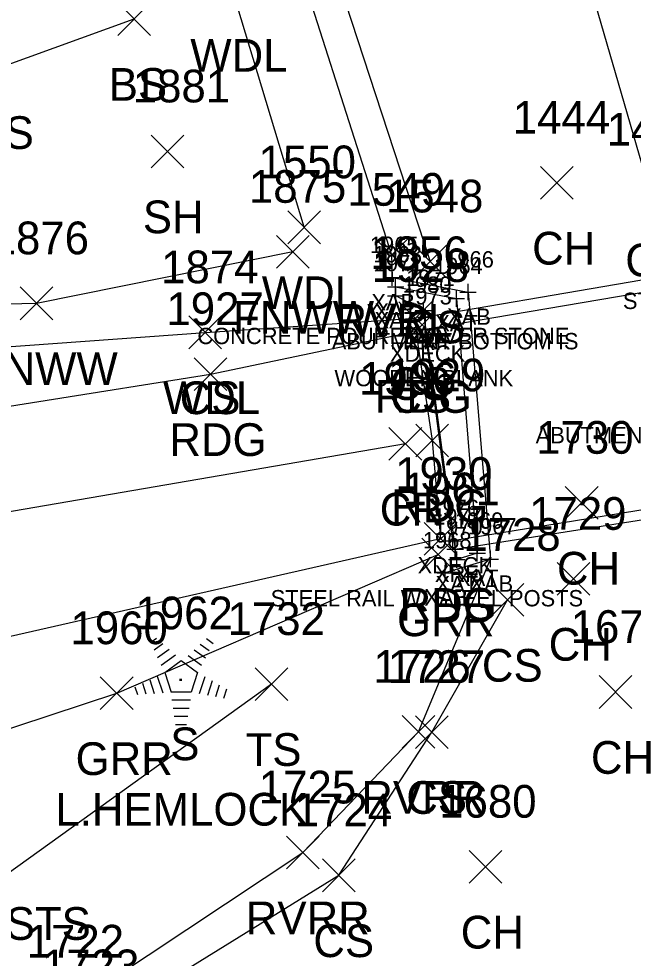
# Model space of a CAD drawing. Extents: x 1621633 to 1624015, y 417863 to 420979.
# Drawn here: x 1621947.4 to 1621985, y 418067.9 to 418125.3 of the extents above; entities that cross this region are included whole.
import ezdxf

# ---------------------------------------------------------------- set-up
doc = ezdxf.new("R2010")
doc.units = 0
for name, color, linetype in [('B_A', 7, 'Continuous'), ('B_C', 7, 'Continuous'), ('B_I', 7, 'Continuous'), ('B_TIC', 7, 'Continuous'), ('BELB', 7, 'Continuous'), ('BR', 7, 'Continuous'), ('BSUBM', 7, 'Continuous'), ('L_A', 7, 'Continuous'), ('L_C', 7, 'Continuous'), ('L_I', 7, 'Continuous'), ('L_TIC', 7, 'Continuous'), ('LAWA', 7, 'Continuous'), ('LAWE', 7, 'Continuous'), ('LELB', 7, 'Continuous'), ('LFNC', 7, 'Continuous'), ('LTC', 7, 'Continuous'), ('P_A', 7, 'Continuous'), ('P_I', 7, 'Continuous'), ('P_TIC', 7, 'Continuous'), ('PEU', 7, 'Continuous'), ('PRC', 7, 'Continuous'), ('R_A', 7, 'Continuous'), ('R_C', 7, 'Continuous'), ('R_I', 7, 'Continuous'), ('R_TIC', 7, 'Continuous'), ('RGR', 7, 'Continuous')]:
    doc.layers.add(name, color=color, linetype=linetype)

msp = doc.modelspace()

# ---------------------------------------------------------------- linework, layer by layer
at = {"layer": 'B_TIC'}
for p, q in [((1621970.273, 418109.501), (1621970.349, 418109.501)), ((1621970.477, 418108.931), (1621970.553, 418108.931)), ((1621974.904, 418108.613), (1621974.98, 418108.613)), ((1621970.487, 418108.387), (1621970.563, 418108.387)), ((1621974.195, 418108.215), (1621974.27, 418108.215)), ((1621972.178, 418107.487), (1621972.254, 418107.487)), ((1621972.304, 418107.07), (1621972.38, 418107.07)), ((1621972.283, 418106.356), (1621972.358, 418106.356)), ((1621973.978, 418093.412), (1621974.053, 418093.412)), ((1621974.116, 418092.897), (1621974.192, 418092.897)), ((1621975.464, 418092.646), (1621975.539, 418092.646)), ((1621974.209, 418092.261), (1621974.284, 418092.261)), ((1621976.265, 418092.293), (1621976.341, 418092.293)), ((1621973.512, 418091.444), (1621973.587, 418091.444))]:
    msp.add_line(p, q, dxfattribs=at)
for points in [[(1621970.27, 418109.001), (1621970.27, 418110.001)], [(1621969.77, 418109.501), (1621970.77, 418109.501)], [(1621970.474, 418108.431), (1621970.474, 418109.431)], [(1621974.901, 418108.113), (1621974.901, 418109.113)], [(1621969.974, 418108.931), (1621970.974, 418108.931)], [(1621970.484, 418107.887), (1621970.484, 418108.887)], [(1621974.191, 418107.715), (1621974.191, 418108.715)], [(1621974.401, 418108.613), (1621975.401, 418108.613)], [(1621969.984, 418108.387), (1621970.984, 418108.387)], [(1621972.175, 418106.987), (1621972.175, 418107.987)], [(1621973.691, 418108.215), (1621974.691, 418108.215)], [(1621971.675, 418107.487), (1621972.675, 418107.487)], [(1621972.301, 418106.57), (1621972.301, 418107.57)], [(1621971.801, 418107.07), (1621972.801, 418107.07)], [(1621972.279, 418105.856), (1621972.279, 418106.856)], [(1621971.779, 418106.356), (1621972.779, 418106.356)], [(1621973.974, 418092.912), (1621973.974, 418093.912)], [(1621973.474, 418093.412), (1621974.474, 418093.412)], [(1621973.613, 418092.897), (1621974.613, 418092.897)], [(1621974.113, 418092.397), (1621974.113, 418093.397)], [(1621975.461, 418092.146), (1621975.461, 418093.146)], [(1621974.205, 418091.761), (1621974.205, 418092.761)], [(1621974.961, 418092.646), (1621975.961, 418092.646)], [(1621976.262, 418091.793), (1621976.262, 418092.793)], [(1621973.508, 418090.944), (1621973.508, 418091.944)], [(1621973.705, 418092.261), (1621974.705, 418092.261)], [(1621975.762, 418092.293), (1621976.762, 418092.293)], [(1621973.008, 418091.444), (1621974.008, 418091.444)]]:
    msp.add_lwpolyline(points, dxfattribs=at)
at = {"layer": 'BELB'}
for points in [[(1621972.279, 418106.356), (1621995.663, 418110.32), (1621997.337, 418097.222), (1621973.974, 418093.412)], [(1621973.974, 418093.412), (1621972.279, 418106.356)]]:
    msp.add_lwpolyline(points, dxfattribs=at)
at = {"layer": 'BR'}
for points in [[(1621995.641, 418111.077), (1621972.301, 418107.07)], [(1621974.113, 418092.897), (1621997.518, 418096.593)]]:
    msp.add_lwpolyline(points, dxfattribs=at)
at = {"layer": 'BSUBM'}
for points in [[(1621970.27, 418109.501), (1621974.901, 418108.613), (1621976.262, 418092.293), (1621973.508, 418091.444)], [(1621970.474, 418108.931), (1621974.191, 418108.215), (1621975.461, 418092.646), (1621974.205, 418092.261), (1621972.175, 418107.487), (1621970.484, 418108.387)]]:
    msp.add_lwpolyline(points, dxfattribs=at)
at = {"layer": 'L_TIC'}
for points in [[(1621953.501, 418124.31), (1621955.501, 418126.31)], [(1621955.501, 418124.31), (1621953.501, 418126.31)], [(1621955.534, 418116.211), (1621957.534, 418118.211)], [(1621957.534, 418116.211), (1621955.534, 418118.211)], [(1621979.328, 418114.296), (1621981.328, 418116.296)], [(1621981.328, 418114.296), (1621979.328, 418116.296)], [(1621963.876, 418111.573), (1621965.876, 418113.573)], [(1621965.876, 418111.573), (1621963.876, 418113.573)], [(1621963.197, 418110.074), (1621965.197, 418112.074)], [(1621965.197, 418110.074), (1621963.197, 418112.074)], [(1621969.23, 418109.893), (1621971.23, 418111.893)], [(1621971.23, 418109.893), (1621969.23, 418111.893)], [(1621971.578, 418109.484), (1621973.578, 418111.484)], [(1621973.578, 418109.484), (1621971.578, 418111.484)], [(1621947.53, 418106.925), (1621949.53, 418108.925)], [(1621949.53, 418106.925), (1621947.53, 418108.925)], [(1621970.677, 418106.015), (1621972.677, 418108.015)], [(1621972.677, 418106.015), (1621970.677, 418108.015)], [(1621957.835, 418105.152), (1621959.835, 418107.152)], [(1621959.835, 418105.152), (1621957.835, 418107.152)], [(1621957.835, 418105.152), (1621959.835, 418107.152)], [(1621959.835, 418105.152), (1621957.835, 418107.152)], [(1621970.708, 418105.231), (1621972.708, 418107.231)], [(1621972.708, 418105.231), (1621970.708, 418107.231)], [(1621980.843, 418094.729), (1621982.843, 418096.729)], [(1621982.843, 418094.729), (1621980.843, 418096.729)], [(1621980.338, 418090.078), (1621982.338, 418092.078)], [(1621982.338, 418090.078), (1621980.338, 418092.078)], [(1621976.304, 418088.793), (1621978.304, 418090.793)], [(1621978.304, 418088.793), (1621976.304, 418090.793)], [(1621961.893, 418083.645), (1621963.893, 418085.645)], [(1621963.893, 418083.645), (1621961.893, 418085.645)], [(1621982.92, 418083.162), (1621984.92, 418085.162)], [(1621984.92, 418083.162), (1621982.92, 418085.162)], [(1621970.864, 418080.724), (1621972.864, 418082.724)], [(1621972.864, 418080.724), (1621970.864, 418082.724)], [(1621971.682, 418080.713), (1621973.682, 418082.713)], [(1621973.682, 418080.713), (1621971.682, 418082.713)], [(1621963.804, 418073.349), (1621965.804, 418075.349)], [(1621965.804, 418073.349), (1621963.804, 418075.349)], [(1621966.003, 418071.955), (1621968.003, 418073.955)], [(1621968.003, 418071.955), (1621966.003, 418073.955)], [(1621974.963, 418072.479), (1621976.963, 418074.479)], [(1621976.963, 418072.479), (1621974.963, 418074.479)]]:
    msp.add_lwpolyline(points, dxfattribs=at)
at = {"layer": 'LAWA'}
for points in [[(1621956.585, 418284.614), (1621944.789, 418263.744), (1621937.989, 418240.815), (1621923.643, 418212.076), (1621903.114, 418191.442), (1621882.695, 418166.672), (1621873.439, 418154.294), (1621850.988, 418135.574), (1621826.172, 418116.057), (1621804.716, 418096.141), (1621776.821, 418074.388), (1621781.781, 418070.723), (1621808.711, 418078.699), (1621829.621, 418083.556), (1621862.329, 418091.327), (1621892.285, 418098.274), (1621914.935, 418102.809), (1621920.305, 418103.098), (1621927.789, 418103.902), (1621958.835, 418106.152)], [(1621964.876, 418112.573), (1621960.506, 418127.086), (1621958.473, 418132.299), (1621952.202, 418163.991), (1621942.417, 418191.539), (1621933.842, 418203.578)]]:
    msp.add_lwpolyline(points, dxfattribs=at)
at = {"layer": 'LAWE'}
for points in [[(1622333.173, 418232.978), (1622304.922, 418224.429), (1622278.58, 418222.596), (1622250.586, 418234.065), (1622231.085, 418250.898), (1622207.089, 418257.628), (1622185.142, 418265.615), (1622157.854, 418271.291), (1622128.424, 418279.107), (1622109.176, 418281.03), (1622103.422, 418276.532), (1622081.068, 418269.588), (1622054.892, 418266.851), (1622024.679, 418262.775), (1621999.348, 418261.337), (1621980.097, 418259.353), (1621959.539, 418247.527), (1621949.109, 418230.907), (1621945.674, 418206.622), (1621950.844, 418182.298), (1621958.694, 418157.035), (1621962.917, 418133.775), (1621970.23, 418110.893)], [(1621970.23, 418110.893), (1621970.27, 418109.501)], [(1621971.864, 418081.724), (1621976.262, 418092.293)], [(1621682.822, 417967.998), (1621698.064, 417979.126), (1621716.448, 417990.621), (1621740.687, 418004.296), (1621760.276, 418012.676), (1621779.786, 418018.1), (1621807.782, 418023.044), (1621832.841, 418028.899), (1621852.452, 418034.783), (1621876.37, 418040.125), (1621904.646, 418043.594), (1621931.259, 418052.925), (1621950.617, 418064.927), (1621964.804, 418074.349), (1621971.864, 418081.724)]]:
    msp.add_lwpolyline(points, dxfattribs=at)
at = {"layer": 'LELB'}
for points in [[(1621986.067, 418114.571), (1621980.007, 418135.511), (1621971.795, 418158.969), (1621964.778, 418178.351), (1621962.014, 418198.432), (1621960.296, 418210.777), (1621971.297, 418225.2), (1621983.839, 418236.143), (1622007.179, 418245.448), (1622025.653, 418246.508), (1622054.037, 418255.072), (1622065.318, 418256.151)], [(1621951.89, 418230.385), (1621950.814, 418206.602), (1621953.261, 418182.888), (1621961.465, 418157.615), (1621964.444, 418135.417), (1621972.578, 418110.484)], [(1621925.719, 418114.299), (1621946.353, 418122.363), (1621954.501, 418125.31)], [(1621958.835, 418106.152), (1621971.677, 418107.015), (1621971.708, 418106.231)], [(1621714.218, 417979.319), (1621742.211, 418002.577), (1621762.579, 418009.214), (1621780.28, 418013.608), (1621808.258, 418019.376), (1621833.473, 418026.83), (1621853.516, 418030.646), (1621878.098, 418035.973), (1621904.446, 418042.094), (1621933.372, 418049.997), (1621951.553, 418063.416), (1621967.003, 418072.955), (1621972.682, 418081.713), (1621977.304, 418089.793)], [(1621962.893, 418084.645), (1621941.499, 418069.284), (1621934.526, 418059.292), (1621911.153, 418049.766), (1621884.836, 418045.66), (1621868.891, 418041.418), (1621850.259, 418038.198), (1621830.712, 418031.899), (1621803.346, 418026.98), (1621784.312, 418024.309)]]:
    msp.add_lwpolyline(points, dxfattribs=at)
at = {"layer": 'LFNC'}
msp.add_lwpolyline([(1621964.197, 418111.074), (1621948.53, 418107.925), (1621925.05, 418107.389), (1621910.629, 418106.254), (1621880.442, 418100.757), (1621858.02, 418096.026), (1621836.432, 418089.427), (1621812.807, 418084.09), (1621788.073, 418077.584)], dxfattribs=at)
at = {"layer": 'LTC'}
for p, q in [((1621955.509, 418087.202), (1621955.864, 418087.46)), ((1621958.907, 418087.442), (1621959.326, 418087.138)), ((1621955.719, 418086.737), (1621956.248, 418087.121)), ((1621955.928, 418086.271), (1621956.632, 418086.782)), ((1621958.165, 418086.746), (1621958.844, 418086.252)), ((1621958.536, 418087.094), (1621959.086, 418086.695)), ((1621956.138, 418085.805), (1621957.016, 418086.443)), ((1621956.362, 418085.35), (1621957.374, 418086.085)), ((1621957.374, 418086.085), (1621958.371, 418085.36)), ((1621957.794, 418086.397), (1621958.604, 418085.809)), ((1621955.452, 418084.915), (1621955.724, 418084.079)), ((1621955.908, 418085.131), (1621956.239, 418084.112)), ((1621956.362, 418085.35), (1621956.749, 418084.157)), ((1621958.371, 418085.36), (1621957.98, 418084.157)), ((1621958.809, 418085.089), (1621958.471, 418084.049)), ((1621954.541, 418084.481), (1621954.694, 418084.013)), ((1621954.997, 418084.698), (1621955.209, 418084.046)), ((1621959.253, 418084.838), (1621958.966, 418083.954)), ((1621959.698, 418084.588), (1621959.461, 418083.859)), ((1621960.142, 418084.338), (1621959.955, 418083.764)), ((1621957.98, 418084.157), (1621956.749, 418084.157)), ((1621957.941, 418083.657), (1621956.797, 418083.657)), ((1621957.858, 418083.157), (1621956.869, 418083.157)), ((1621957.774, 418082.657), (1621956.942, 418082.657)), ((1621957.69, 418082.157), (1621957.015, 418082.157))]:
    msp.add_line(p, q, dxfattribs=at)
at = {"layer": 'P_TIC'}
for points in [[(1621970.708, 418105.231), (1621972.708, 418107.231)], [(1621972.708, 418105.231), (1621970.708, 418107.231)], [(1621958.157, 418102.592), (1621960.157, 418104.592)], [(1621960.157, 418102.592), (1621958.157, 418104.592)], [(1621971.706, 418098.544), (1621973.706, 418100.544)], [(1621973.706, 418098.544), (1621971.706, 418100.544)], [(1621970.067, 418098.341), (1621972.067, 418100.341)], [(1621972.067, 418098.341), (1621970.067, 418100.341)], [(1621972.225, 418092.52), (1621974.225, 418094.52)], [(1621974.225, 418092.52), (1621972.225, 418094.52)]]:
    msp.add_lwpolyline(points, dxfattribs=at)
at = {"layer": 'PEU'}
msp.add_lwpolyline([(1621862.236, 418084.699), (1621894.034, 418092.423), (1621927.67, 418098.576), (1621959.157, 418103.592), (1621971.708, 418106.231), (1621972.706, 418099.544), (1621973.225, 418093.52), (1621943.584, 418086.799), (1621912.204, 418078.592), (1621880.997, 418070.288)], dxfattribs=at)
at = {"layer": 'PRC'}
msp.add_lwpolyline([(1621971.067, 418099.341), (1621938.438, 418093.726), (1621906.629, 418086.952), (1621874.869, 418079.941), (1621842.519, 418071.194), (1621811.531, 418061.42), (1621780.514, 418050.109), (1621750.947, 418035.3), (1621723.041, 418018.53), (1621696.18, 418000.53), (1621670.933, 417981.571)], dxfattribs=at)
at = {"layer": 'R_TIC'}
for points in [[(1621972.073, 418091.576), (1621974.073, 418093.576)], [(1621974.073, 418091.576), (1621972.073, 418093.576)], [(1621952.425, 418083.086), (1621954.425, 418085.086)], [(1621954.425, 418083.086), (1621952.425, 418085.086)]]:
    msp.add_lwpolyline(points, dxfattribs=at)
at = {"layer": 'RGR'}
msp.add_lwpolyline([(1621935.024, 418078.009), (1621953.425, 418084.086), (1621973.073, 418092.576)], dxfattribs=at)

# ---------------------------------------------------------------- texts
at = {"layer": 'B_A'}
for s, p in [('XAB', (1621968.99, 418107.501)), ('XAT', (1621969.178, 418106.931)), ('XAT', (1621969.188, 418106.387)), ('XAB', (1621973.621, 418106.613)), ('XAT', (1621972.896, 418106.215)), ('XAT', (1621970.88, 418105.487)), ('XRF', (1621971.061, 418105.07)), ('XDECK', (1621970.122, 418104.356)), ('XDECK', (1621971.817, 418091.412)), ('XRF', (1621972.873, 418090.897)), ('XAT', (1621972.91, 418090.261)), ('XAT', (1621974.165, 418090.646)), ('XAB', (1621974.982, 418090.293)), ('XAB', (1621972.229, 418089.444))]:
    msp.add_text(s, height=1, dxfattribs=at).set_placement(p)
at = {"layer": 'B_C'}
for s, p in [('STEEL RAIL W/ STEEL POSTS', (1621984.365, 418107.577)), ('CONCRETE POURED OVER STONE', (1621958.355, 418105.431)), ('ABUTMENT BOTTOM IS', (1621966.57, 418105.113)), ('WOODEN PLANK', (1621966.736, 418102.856)), ('ABUTMENT BOTTOM IS UNDERMINED', (1621979.031, 418099.365)), ('STEEL RAIL W/ STEEL POSTS', (1621962.837, 418089.397))]:
    msp.add_text(s, height=1, dxfattribs=at).set_placement(p)
at = {"layer": 'B_I'}
for s, p in [('1965', (1621968.9, 418111.001)), ('1963', (1621969.104, 418110.431)), ('1972', (1621969.137, 418109.887)), ('1964', (1621972.821, 418109.715)), ('1966', (1621973.503, 418110.113)), ('1980', (1621970.911, 418108.57)), ('1971', (1621971.112, 418108.987)), ('1973', (1621970.933, 418107.856)), ('1976', (1621972.6, 418094.912)), ('1977', (1621972.766, 418094.397)), ('1970', (1621972.815, 418093.761)), ('1969', (1621974.086, 418094.146)), ('1967', (1621974.892, 418093.793)), ('1968', (1621972.138, 418092.944))]:
    msp.add_text(s, height=1, dxfattribs=at).set_placement(p)
at = {"layer": 'L_A'}
for s, p in [('WDL', (1621957.923, 418122.086)), ('BS', (1621952.941, 418120.31)), ('BS', (1621944.794, 418117.363)), ('SH', (1621955.023, 418112.211)), ('CH', (1621978.816, 418110.296)), ('CS', (1621984.508, 418109.571)), ('WDL', (1621962.294, 418107.573)), ('FNWW', (1621960.543, 418106.074)), ('RVRL', (1621966.797, 418105.893)), ('CS', (1621971.019, 418105.484)), ('FNWW', (1621944.876, 418102.925)), ('CS', (1621970.117, 418102.015)), ('CS', (1621970.149, 418101.231)), ('WDL', (1621956.252, 418101.152)), ('CS', (1621957.276, 418101.152)), ('CH', (1621980.332, 418090.729)), ('CH', (1621979.826, 418086.078)), ('CS', (1621975.745, 418084.793)), ('S', (1621956.7, 418079.994)), ('TS', (1621961.302, 418079.645)), ('CH', (1621982.409, 418079.162)), ('RVRR', (1621968.376, 418076.724)), ('CS', (1621971.123, 418076.713)), ('RVRR', (1621961.316, 418069.349)), ('CH', (1621974.452, 418068.479)), ('CS', (1621965.444, 418067.955))]:
    msp.add_text(s, height=2, dxfattribs=at).set_placement(p)
at = {"layer": 'L_C'}
msp.add_text('L.HEMLOCK', height=2, dxfattribs=at).set_placement((1621949.676, 418075.994))
at = {"layer": 'L_I'}
for s, p in [('1881', (1621954.408, 418120.211)), ('1444', (1621977.635, 418118.296)), ('1443', (1621983.374, 418117.571)), ('1550', (1621962.097, 418115.573)), ('1875', (1621961.504, 418114.074)), ('1549', (1621967.529, 418113.893)), ('1548', (1621969.885, 418113.484)), ('1876', (1621945.782, 418110.925)), ('1856', (1621968.928, 418110.015)), ('1874', (1621956.142, 418109.152)), ('1874', (1621956.142, 418109.152)), ('1928', (1621969.015, 418109.231)), ('1730', (1621979.064, 418098.729)), ('1729', (1621978.637, 418094.078)), ('1728', (1621974.611, 418092.793)), ('1962', (1621954.574, 418087.994)), ('1732', (1621960.2, 418087.645)), ('1679', (1621981.172, 418087.162)), ('1726', (1621969.116, 418084.724)), ('1727', (1621969.989, 418084.713)), ('1725', (1621962.111, 418077.349)), ('1724', (1621964.31, 418075.955)), ('1680', (1621973.137, 418076.479)), ('1722', (1621947.924, 418067.927)), ('1723', (1621948.861, 418066.416))]:
    msp.add_text(s, height=2, dxfattribs=at).set_placement(p)
at = {"layer": 'LTC'}
msp.add_text('.', height=1.037, rotation=270, dxfattribs=at).set_placement((1621957.256, 418085.098))
at = {"layer": 'P_A'}
for s, p in [('RDG', (1621969.196, 418101.231)), ('RDG', (1621956.645, 418098.592)), ('CR', (1621969.5, 418094.341)), ('RDG', (1621970.194, 418094.544)), ('RDG', (1621970.714, 418088.52))]:
    msp.add_text(s, height=2, dxfattribs=at).set_placement(p)
at = {"layer": 'P_I'}
for s, p in [('1928', (1621969.015, 418109.231)), ('1927', (1621956.464, 418106.592)), ('1906', (1621968.24, 418102.341)), ('1929', (1621970.005, 418102.544)), ('1930', (1621970.446, 418096.52))]:
    msp.add_text(s, height=2, dxfattribs=at).set_placement(p)
at = {"layer": 'R_A'}
for p in [(1621970.561, 418087.576), (1621950.913, 418079.086)]:
    msp.add_text('GRR', height=2, dxfattribs=at).set_placement(p)
at = {"layer": 'R_C'}
msp.add_text('ONE CABLE W/ WOOD POSTS', height=2, dxfattribs=at).set_placement((1621913.355, 418069.009))
at = {"layer": 'R_I'}
for s, p in [('1961', (1621970.9, 418095.576)), ('1960', (1621950.598, 418087.086))]:
    msp.add_text(s, height=2, dxfattribs=at).set_placement(p)

doc.saveas('drawing.dxf')
